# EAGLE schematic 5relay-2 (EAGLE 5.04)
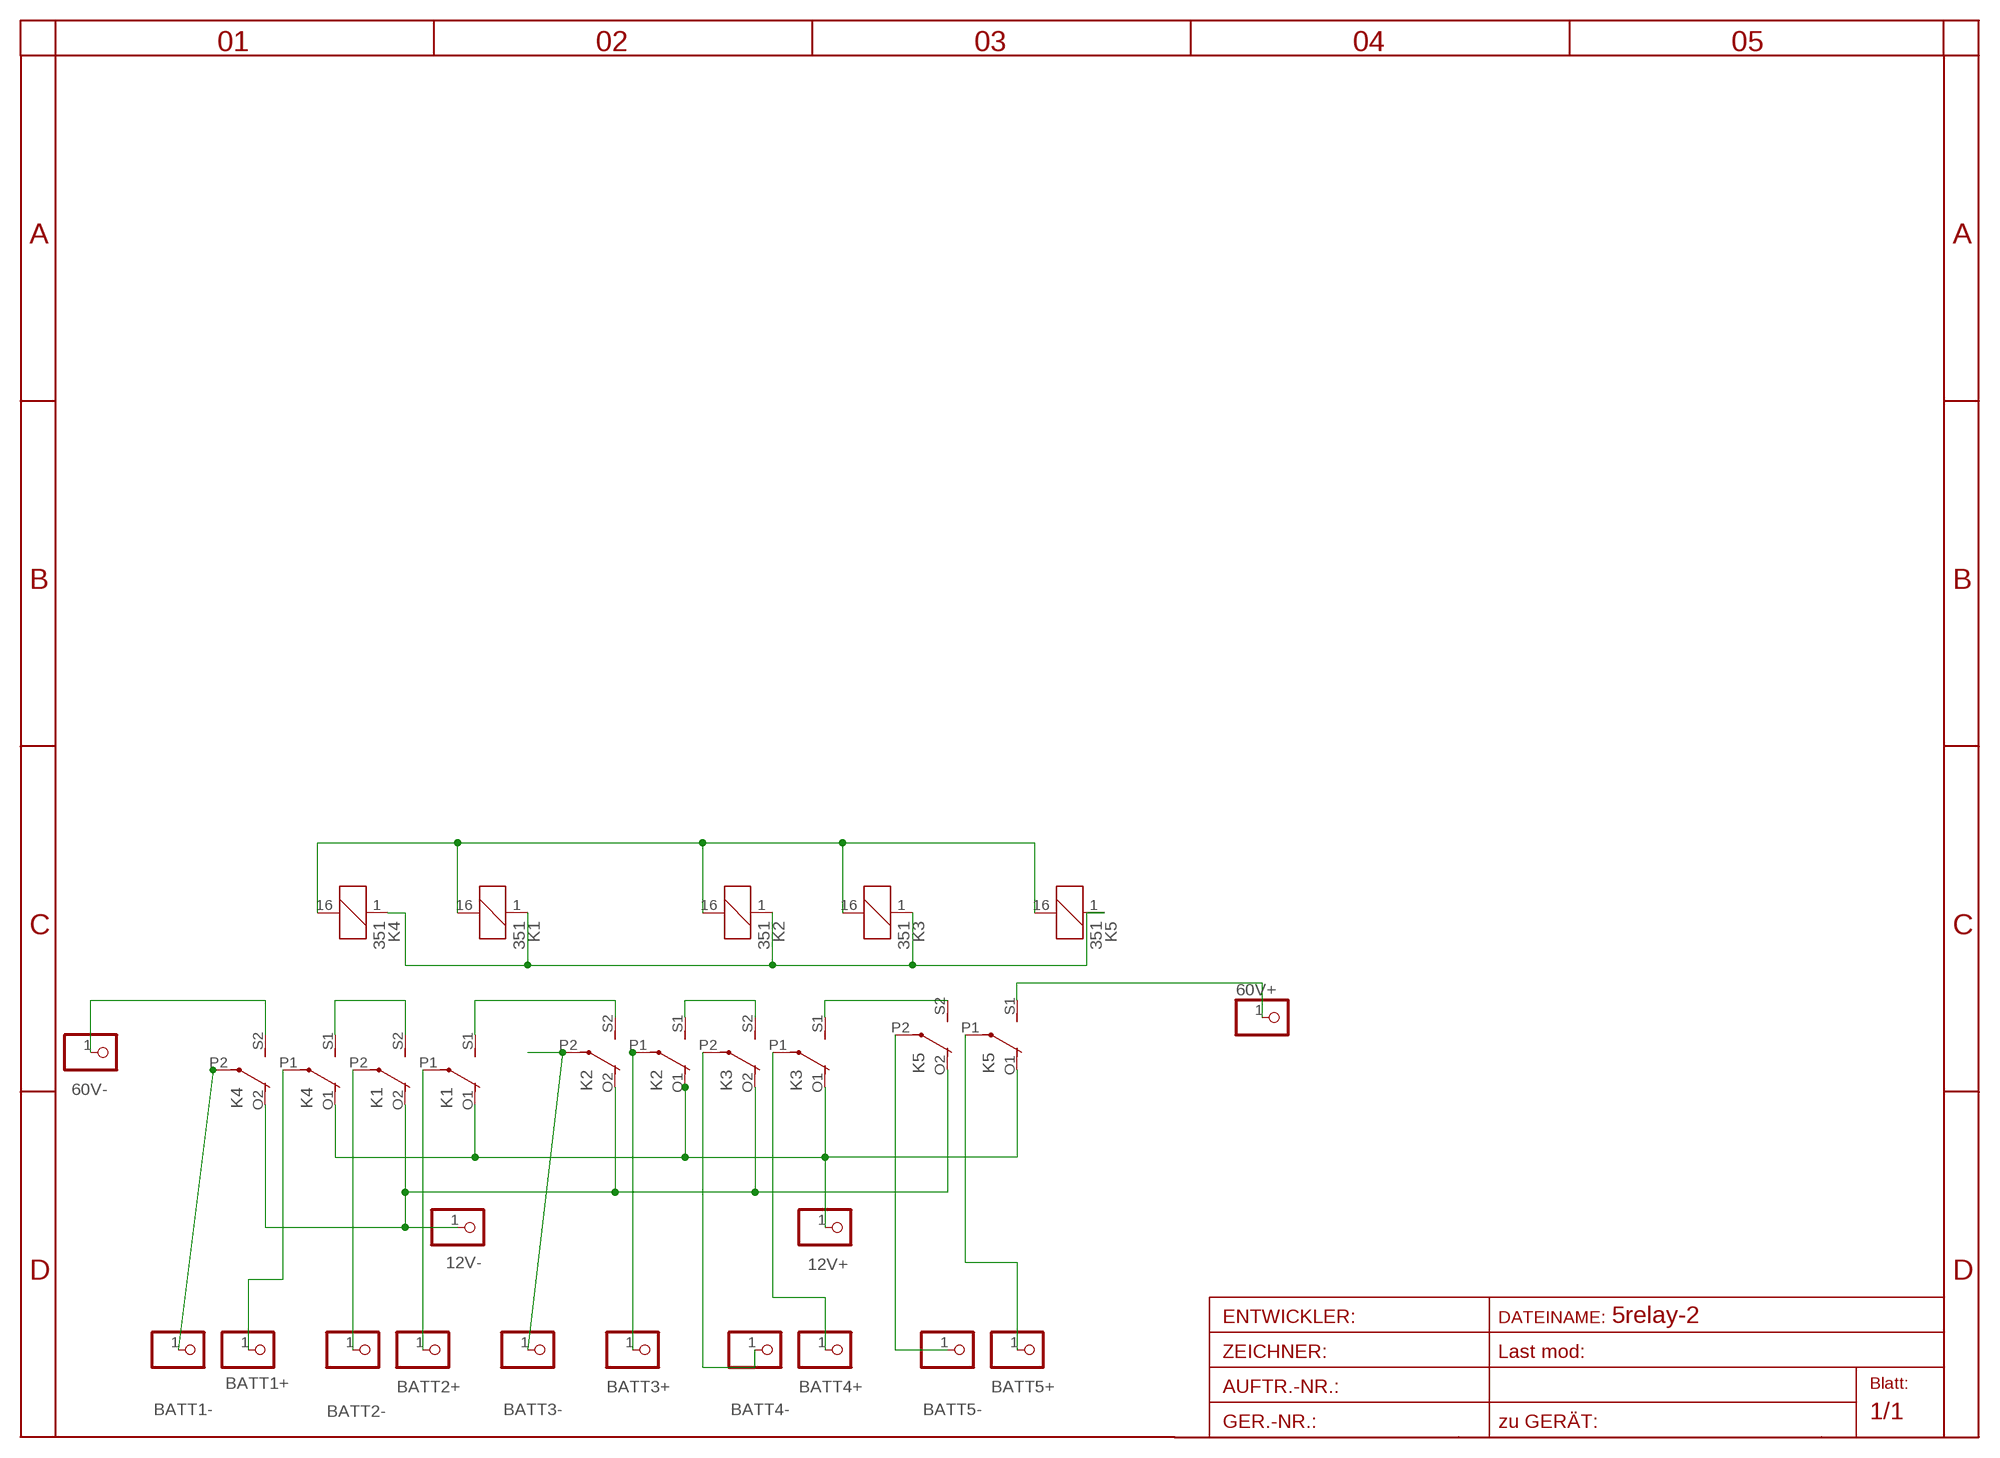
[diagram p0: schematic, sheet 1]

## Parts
12V+  PINHD-1X1  [1X01]
12V-  PINHD-1X1  [1X01]
60V+  PINHD-1X1  [1X01]
60V-  PINHD-1X1  [1X01]
BATT1+  PINHD-1X1  [1X01]
BATT1-  PINHD-1X1  [1X01]
BATT2+  PINHD-1X1  [1X01]
BATT2-  PINHD-1X1  [1X01]
BATT3+  PINHD-1X1  [1X01]
BATT3-  PINHD-1X1  [1X01]
BATT4+  PINHD-1X1  [1X01]
BATT4-  PINHD-1X1  [1X01]
BATT5+  PINHD-1X1  [1X01]
BATT5-  PINHD-1X1  [1X01]
K1  351  [351]
K2  351  [351]
K3  351  [351]
K4  351  [351]
K5  351  [351]

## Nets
BATT1+: BATT1+.1 K4.P1(2:P)
BATT1-: BATT1-.1 K4.P2(3:P)
N$1: K1.16 K2.16 K3.16 K4.16 K5.16
N$2: K1.1 K2.1 K3.1 K4.1 K5.1
N$3: 60V-.1 K4.S2(3:S)
N$4: K1.S2(3:S) K4.S1(2:S)
N$5: K1.S1(2:S) K2.S2(3:S)
N$6: 12V-.1 K1.O2(3:O) K2.O2(3:O) K3.O2(3:O) K4.O2(3:O) K5.O2(3:O)
N$7: 12V+.1 K1.O1(2:O) K2.O1(2:O) K3.O1(2:O) K4.O1(2:O) K5.O1(2:O)
N$8: BATT3-.1 K2.P2(3:P)
N$9: BATT3+.1 K2.P1(2:P)
N$10: BATT2-.1 K1.P2(3:P)
N$11: BATT2+.1 K1.P1(2:P)
N$12: K2.S1(2:S) K3.S2(3:S)
N$13: K3.S1(2:S) K5.S2(3:S)
N$14: 60V+.1 K5.S1(2:S)
N$17: BATT4-.1 K3.P2(3:P)
N$18: BATT4+.1 K3.P1(2:P)
N$19: BATT5-.1 K5.P2(3:P)
N$20: BATT5+.1 K5.P1(2:P)

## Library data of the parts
12V+ 12V- 60V+ 60V- BATT1+ BATT1- BATT2+ BATT2- BATT3+ BATT3- BATT4+ BATT4- BATT5+ BATT5- = pinhead:PINHD-1X1: PIN HEADER
K1-K5 = relay:351: RELAY 2 x switch, Omron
